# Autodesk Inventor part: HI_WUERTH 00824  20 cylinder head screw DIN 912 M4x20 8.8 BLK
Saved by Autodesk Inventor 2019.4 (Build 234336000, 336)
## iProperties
Created: 2021-06
Part Number: HI_WUERTH 00824  20 cylinder head screw DIN 912 M4x20 8.8 BLK
Material: Generic
Document SubType Name: Modeling
Designer: Administrator
Density: 1 g/cm^3
Appearance: Default
Title: HI_WUERTH 00824  20 cylinder head screw DIN 912 M4x20 8.8 BLK
Author: Administrator
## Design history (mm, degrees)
feature "Body1"
body "Solid1"
